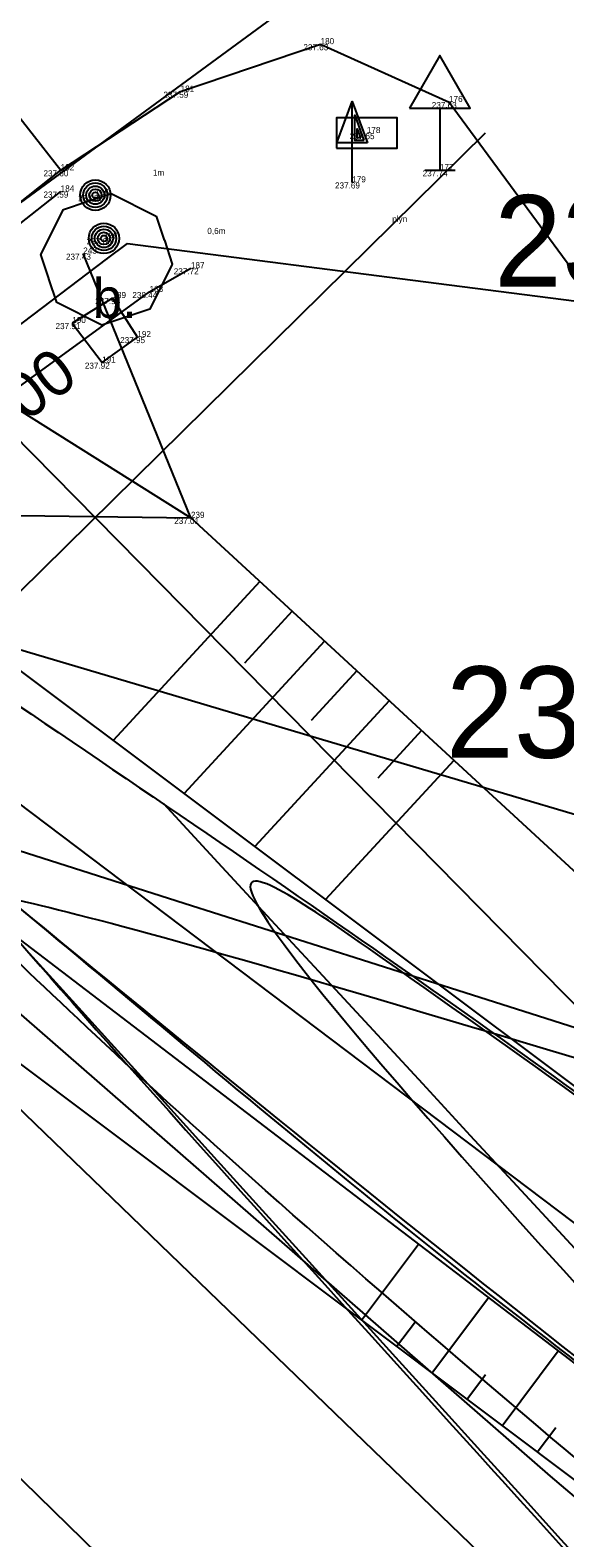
# Model space of a CAD drawing. Extents: x -555757 to -553364, y -1100723 to -1096439.
# Drawn here: x -554302.02 to -554293.24, y -1100536.48 to -1100511.72 of the extents above; entities that cross this region are included whole.
import ezdxf

# ---------------------------------------------------------------- set-up
doc = ezdxf.new("R2010")
doc.units = 0
for name, color, linetype in [('00_NÁVRH - 0.18 mm', 7, 'Continuous'), ('00_NÁVRH - 0.35 mm', 7, 'Continuous'), ('00_NÁVRH - Řezy', 7, 'Continuous'), ('01_HLADINA', 7, 'Continuous'), ('05_SÍTĚ - plynovod STL', 7, 'Continuous'), ('05_SÍTĚ - vedení VN - nadzemní', 7, 'Continuous'), ('30', 7, 'Continuous'), ('56', 7, 'Continuous'), ('8', 7, 'Continuous'), ('DOPRAVNI$ZNACKY', 7, 'Continuous'), ('Geodet. výšky - netisknuté', 7, 'Continuous'), ('HRANA$SVAHU', 7, 'Continuous'), ('HRANICE$PARCELY', 7, 'Continuous'), ('OSA$KOLEJI', 7, 'Continuous'), ('POPIS', 7, 'Continuous'), ('POPIS$POVRCHU', 7, 'Continuous'), ('PRISKA', 7, 'Continuous'), ('ROZHRANI', 7, 'Continuous'), ('SLOUPY', 7, 'Continuous'), ('SVODIDLA', 7, 'Continuous'), ('VOZOVKA', 7, 'Continuous'), ('VYSKA_PODR_BOD', 7, 'Continuous'), ('VYSKOVE$SRAFY', 7, 'Continuous')]:
    doc.layers.add(name, color=color, linetype=linetype)

# ---------------------------------------------------------------- blocks, each defined once
blk = doc.blocks.new('POINT_DISPLAY')
blk.add_line((0, 0), (0, 0))
blk = doc.blocks.new('5$270')
at = {"layer": 'DOPRAVNI$ZNACKY'}
for p, q in [((0, 1.018), (0, 0)), ((-0.25, 0), (0.25, 0))]:
    blk.add_line(p, q, dxfattribs=at)
blk.add_lwpolyline([(-0.5, 1.018), (0.5, 1.018), (0, 1.884)], close=True, dxfattribs=at)
blk = doc.blocks.new('6$66')
at = {"layer": 'PRISKA'}
blk.add_lwpolyline([(-0.5, -0.25), (0.5, -0.25), (0.5, 0.25), (-0.5, 0.25)], close=True, dxfattribs=at)
blk = doc.blocks.new('OS')
at = {"layer": 'SLOUPY'}
for p, q in [((-0.252, 0.652), (0, 1.326)), ((0, 0.652), (-0.252, 0.652)), ((0, 0), (0, 0.65))]:
    blk.add_line(p, q, dxfattribs=at)
for points in [[(0.25, 0.65), (0, 0.65), (0, 1.326), (0, 1.326)], [(0.193, 0.69), (0.04, 0.69), (0.04, 1.103)], [(0.135, 0.73), (0.08, 0.73), (0.08, 0.879)]]:
    blk.add_lwpolyline(points, close=True, dxfattribs=at)
blk = doc.blocks.new('6$01A')
at = {"layer": 'SLOUPY'}
for radius in [0.25, 0.2, 0.15, 0.1, 0.05]:
    blk.add_circle((0, 0), radius, dxfattribs=at)

msp = doc.modelspace()

# ---------------------------------------------------------------- linework, layer by layer
at = {"layer": '00_NÁVRH - 0.18 mm'}
msp.add_lwpolyline([(-554230.466, -1100601.206), (-554249.164, -1100583.038), (-554263.07, -1100566.98), (-554269.426, -1100554.136), (-554270.586, -1100551.573), (-554271.594, -1100550.189), (-554284.219, -1100538.005), (-554306.94, -1100520.848), (-554308.081, -1100519.365), (-554313.597, -1100512.423), (-554314.94, -1100505.715), (-554315.308, -1100495.76), (-554315.472, -1100482.811), (-554315.568, -1100470.17)], dxfattribs=at)
for points in [[(-554058.34, -1100594.24), (-554064.27, -1100591.415), (-554069.894, -1100588.736), (-554070.2, -1100588.59), (-554070.622, -1100588.302), (-554073.49, -1100586.347), (-554075.45, -1100585.01), (-554079.1, -1100582.531), (-554080.049, -1100581.874), (-554080.7, -1100581.481), (-554081.481, -1100581.304), (-554087.875, -1100580.272), (-554092.015, -1100579.605), (-554097.661, -1100578.708), (-554101.142, -1100578.133), (-554103.33, -1100577.967), (-554104.353, -1100578.095), (-554110.104, -1100579.897), (-554119.235, -1100582.7), (-554134.394, -1100587.389), (-554135.14, -1100587.62), (-554135.88, -1100587.767), (-554163.968, -1100593.356), (-554164.64, -1100593.5), (-554165.523, -1100593.676), (-554179.48, -1100596.685), (-554194.32, -1100599.87), (-554206.989, -1100602.104), (-554211.391, -1100602.887), (-554215.452, -1100603.598), (-554218.301, -1100604.127), (-554220.59, -1100604.491), (-554221.645, -1100604.411), (-554222.588, -1100604.119), (-554224.36, -1100602.886), (-554226.55, -1100601.265), (-554230.862, -1100598.151), (-554231.32, -1100597.82), (-554232.374, -1100596.759), (-554235.586, -1100593.426), (-554239.515, -1100589.37), (-554243.986, -1100584.748), (-554247.71, -1100580.92), (-554249.936, -1100577.477), (-554252.665, -1100573.15), (-554257.62, -1100565.38), (-554264.631, -1100555.299), (-554268.645, -1100549.529), (-554269.73, -1100547.97), (-554270.489, -1100547.211), (-554275.85, -1100541.875), (-554281.97, -1100535.78), (-554287.906, -1100531.237), (-554302.937, -1100521.677), (-554058.34, -1100594.24), (-554302.937, -1100521.677)], [(-554047.86, -1100606.09), (-554063.146, -1100601.815), (-554071.814, -1100599.393), (-554074.245, -1100598.71), (-554074.95, -1100598.43), (-554075.799, -1100598.044), (-554076.704, -1100597.516), (-554082.278, -1100594.33), (-554084.54, -1100593.047), (-554085.407, -1100592.634), (-554086.399, -1100592.326), (-554087.509, -1100592.104), (-554096.333, -1100590.269), (-554099.874, -1100589.549), (-554100.557, -1100589.404), (-554101.037, -1100589.369), (-554101.552, -1100589.414), (-554102.59, -1100589.645), (-554107.727, -1100590.768), (-554129.464, -1100595.608), (-554132.384, -1100596.23), (-554132.88, -1100596.318), (-554134.554, -1100596.539), (-554152.022, -1100598.865), (-554161.802, -1100600.155), (-554162.744, -1100600.318), (-554163.338, -1100600.456), (-554165.331, -1100601.02), (-554176.765, -1100604.247), (-554189.626, -1100607.8), (-554194.598, -1100609.179), (-554196.355, -1100609.599), (-554198.704, -1100609.736), (-554203.748, -1100609.834), (-554214.875, -1100610.027), (-554219.792, -1100610.102), (-554223.403, -1100610.173), (-554224.348, -1100610.104), (-554224.869, -1100609.756), (-554225.457, -1100609.217), (-554228.695, -1100606.291), (-554234.196, -1100601.385), (-554241.685, -1100594.776), (-554249.868, -1100587.59), (-554251.102, -1100586.477), (-554253.665, -1100583.954), (-554260.074, -1100577.697), (-554266.777, -1100571.14), (-554267.547, -1100570.379), (-554267.995, -1100569.734), (-554268.443, -1100568.902), (-554268.664, -1100568.278), (-554270.099, -1100564.014), (-554272.97, -1100555.371), (-554273.54, -1100553.674), (-554273.85, -1100553.041), (-554274.307, -1100552.435), (-554274.896, -1100551.869), (-554275.985, -1100550.799), (-554278.698, -1100548.209), (-554284.66, -1100542.226), (-554286.16, -1100540.826), (-554286.536, -1100540.462), (-554286.752, -1100540.28), (-554286.997, -1100540.101), (-554289.311, -1100538.365), (-554299.045, -1100530.122), (-554303.449, -1100525.797), (-554305.461, -1100524.163), (-554047.86, -1100606.09), (-554305.461, -1100524.163)]]:
    msp.add_open_spline(points, degree=3, dxfattribs=at)
at = {"layer": '00_NÁVRH - 0.35 mm'}
for points in [[(-554261.18, -1100566.187), (-554261.287, -1100566.026), (-554262.205, -1100564.307), (-554264.13, -1100560.566), (-554266.956, -1100555.04), (-554269.115, -1100550.897), (-554269.784, -1100549.561), (-554270.23, -1100548.864), (-554270.932, -1100548.082), (-554271.706, -1100547.35), (-554272.831, -1100546.276), (-554274.362, -1100544.823), (-554276.402, -1100542.876), (-554279.345, -1100540.052), (-554281.593, -1100537.929), (-554282.318, -1100537.246), (-554282.905, -1100536.713), (-554283.251, -1100536.425), (-554284.229, -1100535.698), (-554285.73, -1100534.585), (-554286.937, -1100533.66), (-554288.679, -1100532.362), (-554296.351, -1100526.833), (-554303.325, -1100522.059), (-554261.234, -1100566.107), (-554299.826, -1100524.428)], [(-554264.589, -1100568.17), (-554264.717, -1100567.968), (-554265.365, -1100566.881), (-554266.161, -1100565.265), (-554268.948, -1100559.629), (-554270.726, -1100555.972), (-554272.297, -1100552.9), (-554272.836, -1100551.874), (-554273.561, -1100551.08), (-554275.318, -1100549.374), (-554278.961, -1100545.794), (-554283.166, -1100541.692), (-554284.82, -1100540.047), (-554285.492, -1100539.455), (-554286.639, -1100538.528), (-554295.981, -1100531.243), (-554303.386, -1100525.154), (-554305.07, -1100523.778), (-554264.653, -1100568.069), (-554304.227, -1100524.466)]]:
    msp.add_open_spline(points, degree=3, dxfattribs=at)
at = {"layer": '00_NÁVRH - Řezy'}
msp.add_line((-554317.213, -1100535.745), (-554294.542, -1100513.404), dxfattribs=at)
at = {"layer": '01_HLADINA'}
for points in [[(-554303.325, -1100522.059), (-554300.992, -1100523.638), (-554296.049, -1100526.985), (-554290.632, -1100530.919), (-554287.105, -1100533.522), (-554285.641, -1100534.66), (-554284.408, -1100535.575), (-554283.446, -1100536.259), (-554282.815, -1100536.784), (-554282.268, -1100537.291), (-554281.086, -1100538.41), (-554279.101, -1100540.272), (-554276.707, -1100542.588), (-554274.536, -1100544.663), (-554272.962, -1100546.145), (-554271.829, -1100547.242), (-554270.928, -1100548.07), (-554270.249, -1100548.784), (-554269.657, -1100549.746), (-554268.678, -1100551.862), (-554266.678, -1100555.472), (-554264.463, -1100559.99), (-554262.518, -1100563.617), (-554261.613, -1100565.54), (-554261.216, -1100566.134), (-554261.18, -1100566.187)], [(-554265.965, -1100565.681), (-554266.03, -1100565.542), (-554266.988, -1100563.505), (-554268.662, -1100560.317), (-554270.589, -1100556.128), (-554272, -1100553.616), (-554272.759, -1100551.855), (-554273.895, -1100550.757), (-554275.953, -1100548.764), (-554279.126, -1100545.594), (-554282.36, -1100542.557), (-554284.454, -1100540.357), (-554285.634, -1100539.323), (-554289.349, -1100536.38), (-554295.457, -1100531.794), (-554301.469, -1100526.714), (-554304.508, -1100524.236), (-554305.07, -1100523.778)]]:
    msp.add_open_spline(points, degree=3, dxfattribs=at)
at = {"layer": '05_SÍTĚ - plynovod STL'}
for points in [[(-554315.112, -1100526.36), (-554312.77, -1100524.585), (-554300.767, -1100515.483), (-554300.424, -1100515.223)], [(-554300.424, -1100515.223), (-554295.137, -1100515.901), (-554288.092, -1100516.805), (-554269.949, -1100519.132), (-554251.509, -1100528.104)]]:
    msp.add_lwpolyline(points, dxfattribs=at)
at = {"layer": '05_SÍTĚ - vedení VN - nadzemní'}
msp.add_lwpolyline([(-554324.546, -1100507.473), (-554320.113, -1100512.256), (-554293.478, -1100535.466), (-554257.717, -1100565.776), (-554219.756, -1100599.256), (-554187.611, -1100626.856)], dxfattribs=at)
at = {"layer": '56'}
msp.add_lwpolyline([(-554300.767, -1100515.483), (-554300.766, -1100515.486)], dxfattribs=at)
at = {"layer": '8'}
msp.add_lwpolyline([(-554299.949, -1100514.774), (-554299.818, -1100515.167), (-554299.817, -1100515.17), (-554299.686, -1100515.563), (-554300.057, -1100516.304), (-554300.45, -1100516.435), (-554300.843, -1100516.566), (-554301.584, -1100516.195), (-554301.715, -1100515.802), (-554301.716, -1100515.799), (-554301.847, -1100515.406), (-554301.476, -1100514.665), (-554301.083, -1100514.534), (-554300.69, -1100514.403)], close=True, dxfattribs=at)
at = {"layer": 'HRANA$SVAHU'}
for p, q in [((-554299.38, -1100519.73), (-554301.15, -1100515.39)), ((-554303.67, -1100517.04), (-554299.38, -1100519.73)), ((-554282.9, -1100536.69), (-554305.87, -1100519.48)), ((-554302.85, -1100519.68), (-554299.38, -1100519.73)), ((-554281.97, -1100535.78), (-554299.38, -1100519.73)), ((-554308.19, -1100522.08), (-554285.5, -1100539.4)), ((-554308.62, -1100523.87), (-554286.53, -1100540.45))]:
    msp.add_line(p, q, dxfattribs=at)
at = {"layer": 'HRANICE$PARCELY'}
msp.add_line((-554293.88, -1100537.46), (-554310.88, -1100521.06), dxfattribs=at)
for points in [[(-554265.1, -1100458.84), (-554295.16, -1100509.4), (-554304.43, -1100516.2)], [(-554304.43, -1100516.2), (-554284.85, -1100536.07), (-554272.37, -1100550.38)], [(-554293.88, -1100537.46), (-554296.99, -1100540.58), (-554304.83, -1100532.92), (-554308.45, -1100536.59), (-554310.24, -1100536.24), (-554310.38, -1100536.1), (-554314.25, -1100539.99), (-554314.13, -1100540.12), (-554314.82, -1100540.79), (-554313.62, -1100541.84), (-554316.06, -1100544.31), (-554329.35, -1100534.66)]]:
    msp.add_lwpolyline(points, dxfattribs=at)
at = {"layer": 'POPIS'}
for p, q in [((-554300.06, -1100516.02), (-554299.38, -1100515.63)), ((-554310.6, -1100523.66), (-554300.06, -1100516.02))]:
    msp.add_line(p, q, dxfattribs=at)
at = {"layer": 'ROZHRANI'}
for p, q in [((-554304.494, -1100516.378), (-554301.52, -1100514.02)), ((-554300.67, -1100516.12), (-554301.33, -1100516.53)), ((-554300.26, -1100516.76), (-554300.67, -1100516.12)), ((-554301.33, -1100516.53), (-554300.84, -1100517.18)), ((-554300.84, -1100517.18), (-554300.26, -1100516.76))]:
    msp.add_line(p, q, dxfattribs=at)
at = {"layer": 'SVODIDLA'}
msp.add_line((-554311.34, -1100522.1), (-554301.52, -1100514.37), dxfattribs=at)
at = {"layer": 'VOZOVKA'}
for p, q in [((-554299.55, -1100512.73), (-554297.25, -1100511.95)), ((-554297.25, -1100511.95), (-554295.14, -1100512.9)), ((-554302.81, -1100512.37), (-554301.52, -1100514.02)), ((-554301.52, -1100514.02), (-554299.55, -1100512.73)), ((-554295.14, -1100512.9), (-554292.85, -1100516.01))]:
    msp.add_line(p, q, dxfattribs=at)
at = {"layer": 'VYSKOVE$SRAFY'}
for p, q in [((-554298.248, -1100520.773), (-554300.657, -1100523.386)), ((-554297.717, -1100521.263), (-554298.502, -1100522.117)), ((-554297.185, -1100521.753), (-554299.494, -1100524.257)), ((-554296.654, -1100522.243), (-554297.406, -1100523.06)), ((-554296.122, -1100522.733), (-554298.331, -1100525.129)), ((-554295.591, -1100523.223), (-554296.31, -1100524.004)), ((-554295.059, -1100523.713), (-554297.168, -1100526)), ((-554296.579, -1100532.908), (-554295.643, -1100531.658)), ((-554295.424, -1100533.774), (-554294.493, -1100532.535)), ((-554296.002, -1100533.341), (-554295.691, -1100532.926)), ((-554294.269, -1100534.641), (-554293.347, -1100533.41)), ((-554294.847, -1100534.208), (-554294.538, -1100533.796)), ((-554293.692, -1100535.074), (-554293.384, -1100534.667))]:
    msp.add_line(p, q, dxfattribs=at)

# ---------------------------------------------------------------- block references
at = {"layer": 'DOPRAVNI$ZNACKY'}
msp.add_blockref('5$270', (-554295.29, -1100514.02), dxfattribs=at)
at = {"layer": 'PRISKA'}
msp.add_blockref('6$66', (-554296.49, -1100513.41), dxfattribs=at)
at = {"layer": 'ROZHRANI'}
for p in [(-554297.25, -1100511.95), (-554299.55, -1100512.73), (-554295.14, -1100512.9), (-554296.49, -1100513.41), (-554301.52, -1100514.02), (-554295.29, -1100514.02), (-554301.52, -1100514.37), (-554296.73, -1100514.22), (-554300.95, -1100514.43), (-554300.81, -1100515.14), (-554301.15, -1100515.39), (-554299.38, -1100515.63), (-554300.67, -1100516.12), (-554300.06, -1100516.02), (-554301.33, -1100516.53), (-554300.26, -1100516.76), (-554300.84, -1100517.18), (-554299.38, -1100519.73)]:
    msp.add_blockref('POINT_DISPLAY', p, dxfattribs=at)
at = {"layer": 'SLOUPY'}
for name, p in [('OS', (-554296.73, -1100514.22)), ('6$01A', (-554300.95, -1100514.43)), ('6$01A', (-554300.81, -1100515.14))]:
    msp.add_blockref(name, p, dxfattribs=at)

# ---------------------------------------------------------------- texts
at = {"layer": '30'}
msp.add_text('Ocel/300', height=0.75, rotation=37.1734, dxfattribs=at).set_placement((-554304.395, -1100519.913))
at = {"layer": 'Geodet. výšky - netisknuté'}
for s, p in [('237.63', (-554297.533, -1100512.05)), ('237.59', (-554299.833, -1100512.83)), ('237.63', (-554295.423, -1100513)), ('237.65', (-554296.773, -1100513.51)), ('237.60', (-554301.803, -1100514.12)), ('1m', (-554300.005, -1100514.109)), ('237.74', (-554295.573, -1100514.12)), ('237.59', (-554301.803, -1100514.47)), ('237.69', (-554297.013, -1100514.32)), ('237.53', (-554301.233, -1100514.53)), ('plyn', (-554296.073, -1100514.869)), ('237.60', (-554301.093, -1100515.24)), ('0,6m', (-554299.111, -1100515.067)), ('237.43', (-554301.433, -1100515.49)), ('237.72', (-554299.663, -1100515.73)), ('237.94', (-554300.953, -1100516.22)), ('238.44', (-554300.343, -1100516.12)), ('237.91', (-554301.605, -1100516.63)), ('237.95', (-554300.543, -1100516.86)), ('237.92', (-554301.123, -1100517.28)), ('237.01', (-554299.655, -1100519.83))]:
    msp.add_text(s, height=0.1, dxfattribs=at).set_placement(p)
at = {"layer": 'OSA$KOLEJI'}
for s, p in [('180', (-554297.25, -1100511.95)), ('181', (-554299.55, -1100512.73)), ('176', (-554295.14, -1100512.9)), ('178', (-554296.49, -1100513.41)), ('182', (-554301.52, -1100514.02)), ('177', (-554295.29, -1100514.02)), ('179', (-554296.73, -1100514.22)), ('184', (-554301.52, -1100514.37)), ('185', (-554300.95, -1100514.43)), ('186', (-554300.81, -1100515.14)), ('243', (-554301.15, -1100515.39)), ('187', (-554299.38, -1100515.63)), ('189', (-554300.67, -1100516.12)), ('188', (-554300.06, -1100516.02)), ('190', (-554301.33, -1100516.53)), ('192', (-554300.26, -1100516.76)), ('191', (-554300.84, -1100517.18)), ('239', (-554299.38, -1100519.73))]:
    msp.add_text(s, height=0.1, dxfattribs=at).set_placement(p)
at = {"layer": 'POPIS$POVRCHU'}
msp.add_text('b.', height=0.65, dxfattribs=at).set_placement((-554300.995, -1100516.445))
at = {"layer": 'VYSKA_PODR_BOD'}
for s, p in [('237.60', (-554294.4, -1100515.93)), ('237.69', (-554295.19, -1100523.67))]:
    msp.add_text(s, height=1.5, dxfattribs=at).set_placement(p)

doc.saveas('drawing.dxf')
